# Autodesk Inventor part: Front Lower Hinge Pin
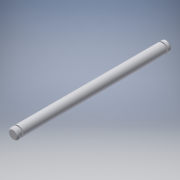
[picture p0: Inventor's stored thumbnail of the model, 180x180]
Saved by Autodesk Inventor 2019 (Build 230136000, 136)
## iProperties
Shininess: 50.0
Compacted: True
Length Units: 11272
Angle Units: 11279
Time Units: 11290
Mass Units: 11286
Length Display Precision: 4
Angle Display Precision: 2
Company: Autodesk
Created: 2000-06
Part Number: Front Lower Hinge Pin
Project: Inventor Samples
Document SubType Name: Modeling
Designer: Autodesk, Inc.
Density: 2.71 g/cm^3
Mass: 0.99953 g
Surface Area: 4.92611 cm^2
Volume: 0.36883 cm^3
Material: Aluminum-6061
Appearance: Light Grey
Density: 0.0
Volumn: 0.0
Area: 0.0
PropertySet Name: Model Information
Control State: 0
Master: False
Checked Out: False
Checked Out Date: 2018-05-30
Last Check In Date: 2018-05-30
Author: Autodesk, Inc.
Revision Number: A
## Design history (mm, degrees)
node "Extrusion1" dims "d1" = 43.78452, "d2" = 0
  sketch "Sketch2"
    geometry: C1 r 1.587 at (-3.385, 8.562)
    constraints: 1 centre point
    dimensions: "d0" = 3.175 diameter of C1
node "Extrusion2" dims "d4" = 0.381, "d5" = 0
  sketch "Sketch3"
    geometry: C1 r 1.587 at (0, 0) reference; C2 r 1.191 at (0, 0)
    constraints: 1 centre point, 1 coincident
    dimensions: "d3" = 2.38252 diameter of C2
node "Extrusion3" dims "d6" = 1.27, "d7" = 0
  sketch "Sketch4"
    geometry: C1 r 1.587 at (0, 0) reference
node "Chamfer1" dims "d8" = 0.381, "d9" = 0.381, "d17" = 45 deg
node "Extrusion4" dims "d11" = 0.381, "d12" = 0
  sketch "Sketch5"
    geometry: C1 r 1.587 at (0, 0) reference; C2 r 1.191 at (0, 0)
    constraints: 1 centre point, 1 coincident
    dimensions: "d10" = 2.38252 diameter of C2
node "Extrusion5" dims "d13" = 1.27, "d14" = 0
  sketch "Sketch6"
    geometry: C1 r 1.587 at (0, 0) reference
node "Chamfer2" dims "d15" = 0.381, "d16" = 0.381, "d18" = 45 deg
body "Solid1"
